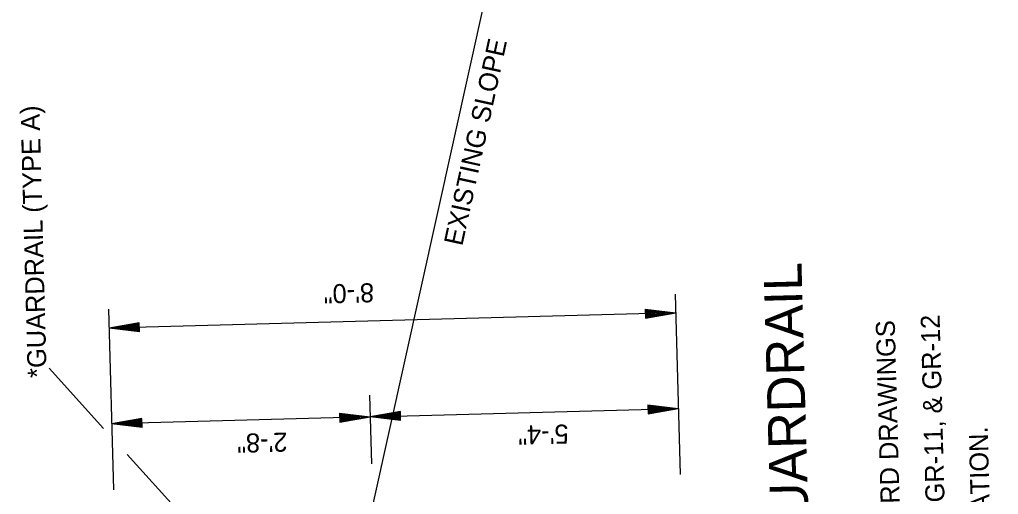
# Model space of a CAD drawing. Extents: x 1929624 to 1935547, y 596315 to 605721.
# Drawn here: x 1932253.7 to 1932563.1, y 600691.9 to 600841.9 of the extents above; entities that cross this region are included whole.
import ezdxf

# ---------------------------------------------------------------- set-up
doc = ezdxf.new("R2010")
doc.units = 0
doc.layers.add('Default', color=7, linetype='Continuous')

msp = doc.modelspace()

# ---------------------------------------------------------------- linework, layer by layer
at = {"layer": 'Default'}
for p, q in [((1932365.29, 600687.8), (1932409.04, 600885.31)), ((1932460.94, 600755.18), (1932462.47, 600698.15)), ((1932281.84, 600750.37), (1932283.37, 600693.34)), ((1932451.47, 600750.38), (1932461.1, 600749.2)), ((1932451.47, 600750.38), (1932451.54, 600747.5)), ((1932451.47, 600750.14), (1932459.5, 600749.16)), ((1932461.1, 600749.2), (1932282, 600744.39)), ((1932451.48, 600749.9), (1932457.85, 600749.11)), ((1932451.49, 600749.66), (1932456.25, 600749.07)), ((1932451.49, 600749.41), (1932454.62, 600749.03)), ((1932451.5, 600749.17), (1932453.02, 600748.98)), ((1932451.51, 600748.72), (1932453.02, 600748.98)), ((1932451.52, 600748.23), (1932456.25, 600749.07)), ((1932451.52, 600748.47), (1932454.62, 600749.03)), ((1932451.53, 600747.99), (1932457.85, 600749.11)), ((1932451.54, 600747.5), (1932461.1, 600749.2)), ((1932451.54, 600747.74), (1932459.5, 600749.16)), ((1932291.56, 600746.09), (1932282, 600744.39)), ((1932291.63, 600743.21), (1932282, 600744.39)), ((1932291.56, 600745.85), (1932283.6, 600744.43)), ((1932291.63, 600743.45), (1932283.6, 600744.43)), ((1932291.57, 600745.6), (1932285.25, 600744.48)), ((1932291.62, 600743.69), (1932285.25, 600744.48)), ((1932291.58, 600745.36), (1932286.85, 600744.52)), ((1932291.61, 600743.93), (1932286.85, 600744.52)), ((1932291.58, 600745.12), (1932288.48, 600744.57)), ((1932291.61, 600744.18), (1932288.48, 600744.57)), ((1932291.59, 600744.87), (1932290.08, 600744.61)), ((1932291.6, 600744.42), (1932290.08, 600744.61)), ((1932291.63, 600743.21), (1932291.56, 600746.09)), ((1932280.28, 600712.75), (1932263.09, 600731.75)), ((1932364.34, 600723.27), (1932364.92, 600701.5)), ((1932452.28, 600720.16), (1932461.91, 600718.98)), ((1932452.28, 600720.16), (1932452.36, 600717.28)), ((1932452.28, 600719.92), (1932460.31, 600718.93)), ((1932452.29, 600719.67), (1932458.66, 600718.89)), ((1932452.3, 600719.43), (1932457.06, 600718.85)), ((1932452.3, 600719.18), (1932455.44, 600718.8)), ((1932364.52, 600716.36), (1932282.81, 600714.17)), ((1932354.89, 600717.54), (1932364.52, 600716.36)), ((1932354.89, 600717.54), (1932354.97, 600714.66)), ((1932354.9, 600717.3), (1932362.92, 600716.32)), ((1932354.9, 600717.06), (1932361.27, 600716.27)), ((1932354.91, 600716.82), (1932359.67, 600716.23)), ((1932354.91, 600716.57), (1932358.05, 600716.19)), ((1932354.92, 600716.33), (1932356.44, 600716.14)), ((1932354.93, 600715.88), (1932356.44, 600716.14)), ((1932354.94, 600715.63), (1932358.05, 600716.19)), ((1932354.95, 600715.15), (1932361.27, 600716.27)), ((1932354.95, 600715.39), (1932359.67, 600716.23)), ((1932354.96, 600714.9), (1932362.92, 600716.32)), ((1932354.97, 600714.66), (1932364.52, 600716.36)), ((1932364.52, 600716.36), (1932461.91, 600718.98)), ((1932374.08, 600718.06), (1932364.52, 600716.36)), ((1932374.16, 600715.18), (1932364.52, 600716.36)), ((1932374.09, 600717.82), (1932366.13, 600716.4)), ((1932374.15, 600715.42), (1932366.13, 600716.4)), ((1932374.09, 600717.57), (1932367.78, 600716.45)), ((1932374.15, 600715.66), (1932367.78, 600716.45)), ((1932374.1, 600717.33), (1932369.38, 600716.49)), ((1932374.14, 600715.9), (1932369.38, 600716.49)), ((1932374.11, 600717.09), (1932371, 600716.54)), ((1932374.13, 600716.15), (1932371, 600716.54)), ((1932374.11, 600716.84), (1932372.6, 600716.58)), ((1932374.13, 600716.39), (1932372.6, 600716.58)), ((1932374.16, 600715.18), (1932374.08, 600718.06)), ((1932452.31, 600718.94), (1932453.83, 600718.76)), ((1932452.32, 600718.49), (1932453.83, 600718.76)), ((1932452.33, 600718.25), (1932455.44, 600718.8)), ((1932452.34, 600717.76), (1932458.66, 600718.89)), ((1932452.34, 600718), (1932457.06, 600718.85)), ((1932452.35, 600717.52), (1932460.31, 600718.93)), ((1932452.36, 600717.28), (1932461.91, 600718.98)), ((1932292.37, 600715.86), (1932282.81, 600714.17)), ((1932292.44, 600712.99), (1932282.81, 600714.17)), ((1932292.37, 600715.62), (1932284.41, 600714.21)), ((1932292.44, 600713.23), (1932284.41, 600714.21)), ((1932292.38, 600715.38), (1932286.06, 600714.25)), ((1932292.43, 600713.47), (1932286.06, 600714.25)), ((1932292.39, 600715.14), (1932287.66, 600714.3)), ((1932292.42, 600713.71), (1932287.66, 600714.3)), ((1932292.39, 600714.9), (1932289.29, 600714.34)), ((1932292.42, 600713.96), (1932289.29, 600714.34)), ((1932292.4, 600714.65), (1932290.89, 600714.38)), ((1932292.41, 600714.2), (1932290.89, 600714.38)), ((1932292.44, 600712.99), (1932292.37, 600715.86)), ((1932308.96, 600681.05), (1932287.75, 600704.49))]:
    msp.add_line(p, q, dxfattribs=at)

# ---------------------------------------------------------------- texts
for s, height, rotation, p in [('EXISTING SLOPE', 6, 77.6663, (1932393.64, 600770.12)), ('*GUARDRAIL (TYPE A)', 6, 91.5377, (1932262.31, 600728.77)), ('SECTION DETAIL FOR GUARDRAIL', 12, 91.5377, (1932508.06, 600496.99)), ('8\'-0"', 6, 181.5377, (1932365.69, 600758.61)), ('GR-8, GR-9, GR-9A, GR-10, GR-11, & GR-12', 6, 91.5377, (1932548.9, 600585.14)), ('NOTE:  REFER TO STANDARD DRAWINGS ', 6, 91.5377, (1932534.68, 600584.76)), ('5\'-4"', 6, 181.5377, (1932427.18, 600713.98)), ('2\'-8"', 6, 181.5377, (1932338.34, 600711.43)), ('FOR ADDITIONAL INFORMATION.', 6, 91.5377, (1932563.12, 600585.52))]:
    msp.add_text(s, height=height, rotation=rotation, dxfattribs=at).set_placement(p)

doc.saveas('drawing.dxf')
